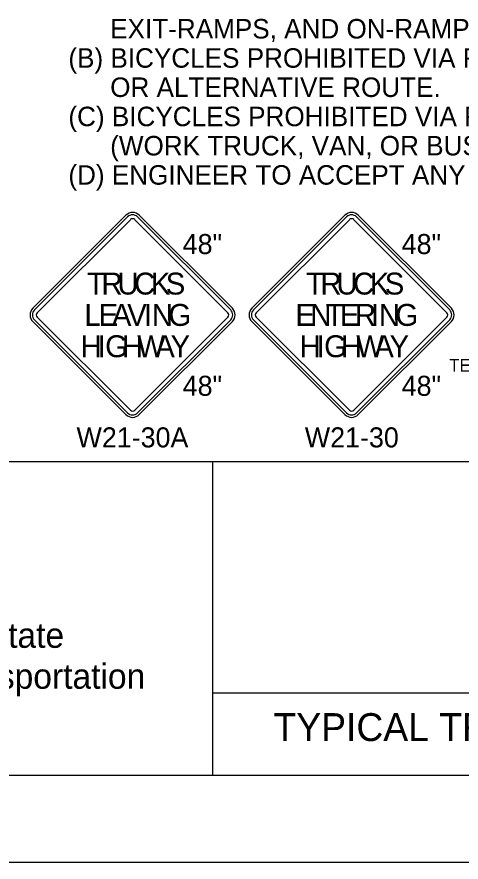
# Model space of a CAD drawing. Extents: x 99999 to 100116, y 99995 to 100013.
# Drawn here: x 100031.504 to 100033.098, y 99999.687 to 100002.723 of the extents above; entities that cross this region are included whole.
import ezdxf

# ---------------------------------------------------------------- set-up
doc = ezdxf.new("R2010")
doc.units = 0
for name, color, linetype in [('SH_GI_GeneralNotesBodyText', 7, 'Continuous'), ('SH_GI_PlotLimits', 7, 'Continuous'), ('SH_GI_SheetBorder', 7, 'Continuous'), ('SH_GI_SheetTextInCells', 7, 'Continuous'), ('SH_GI_TitleBlockText', 7, 'Continuous'), ('TR_SN_ConstructionSigns', 7, 'Continuous')]:
    doc.layers.add(name, color=color, linetype=linetype)

msp = doc.modelspace()

# ---------------------------------------------------------------- linework, layer by layer
at = {"layer": 'SH_GI_PlotLimits'}
msp.add_lwpolyline([(100019.0625, 99999.6875), (100036.0625, 99999.6875), (100036.0625, 100010.6875), (100019.0625, 100010.6875)], close=True, dxfattribs=at)
at = {"layer": 'SH_GI_SheetBorder'}
for p, q in [((100020, 100001.1259), (100035.75, 100001.1259)), ((100032.2055, 100001.1259), (100032.2055, 100000)), ((100032.2055, 100000.2955), (100035.2079, 100000.2955)), ((100020, 100000), (100035.75, 100000))]:
    msp.add_line(p, q, dxfattribs=at)
at = {"layer": 'TR_SN_ConstructionSigns'}
for p, q in [((100031.8955, 100002.0107), (100031.5613, 100001.6766)), ((100031.9014, 100002.0048), (100031.5673, 100001.6707)), ((100032.2713, 100001.6707), (100031.9372, 100002.0048)), ((100032.2773, 100001.6766), (100031.9432, 100002.0107)), ((100032.6812, 100002.0107), (100032.3471, 100001.6766)), ((100032.6871, 100002.0048), (100032.353, 100001.6707)), ((100033.057, 100001.6707), (100032.7229, 100002.0048)), ((100033.063, 100001.6766), (100032.7289, 100002.0107)), ((100031.5773, 100001.6607), (100031.9114, 100001.9948)), ((100031.9273, 100001.9948), (100032.2614, 100001.6607)), ((100032.363, 100001.6607), (100032.6971, 100001.9948)), ((100032.713, 100001.9948), (100033.0471, 100001.6607)), ((100031.9114, 100001.3107), (100031.5773, 100001.6448)), ((100032.2614, 100001.6448), (100031.9273, 100001.3107)), ((100032.6971, 100001.3107), (100032.363, 100001.6448)), ((100033.0471, 100001.6448), (100032.713, 100001.3107)), ((100031.5613, 100001.6289), (100031.8955, 100001.2948)), ((100031.5673, 100001.6349), (100031.9014, 100001.3008)), ((100031.9372, 100001.3008), (100032.2713, 100001.6349)), ((100031.9432, 100001.2948), (100032.2773, 100001.6289)), ((100032.3471, 100001.6289), (100032.6812, 100001.2948)), ((100032.353, 100001.6349), (100032.6871, 100001.3008)), ((100032.7229, 100001.3008), (100033.057, 100001.6349)), ((100032.7289, 100001.2948), (100033.063, 100001.6289))]:
    msp.add_line(p, q, dxfattribs=at)
for centre, radius, start, end in [((100031.9193, 100001.9869), 0.0338, 45, 135), ((100031.9193, 100001.9869), 0.0253, 45, 135), ((100032.705, 100001.9869), 0.0338, 45, 135), ((100032.705, 100001.9869), 0.0253, 45, 135), ((100031.9193, 100001.9869), 0.0113, 45, 135), ((100032.705, 100001.9869), 0.0113, 45, 135), ((100031.5852, 100001.6528), 0.0338, 135, 225), ((100031.5852, 100001.6528), 0.0253, 135, 225), ((100032.2534, 100001.6528), 0.0253, 315, 45), ((100032.2534, 100001.6528), 0.0338, 315, 45), ((100032.3709, 100001.6528), 0.0338, 135, 225), ((100032.3709, 100001.6528), 0.0253, 135, 225), ((100033.0391, 100001.6528), 0.0253, 315, 45), ((100033.0391, 100001.6528), 0.0338, 315, 45), ((100031.5852, 100001.6528), 0.0113, 135, 225), ((100032.2534, 100001.6528), 0.0113, 315, 45), ((100032.3709, 100001.6528), 0.0113, 135, 225), ((100033.0391, 100001.6528), 0.0113, 315, 45), ((100031.9193, 100001.3187), 0.0113, 225, 315), ((100032.705, 100001.3187), 0.0113, 225, 315), ((100031.9193, 100001.3187), 0.0338, 225, 315), ((100031.9193, 100001.3187), 0.0253, 225, 315), ((100032.705, 100001.3187), 0.0338, 225, 315), ((100032.705, 100001.3187), 0.0253, 225, 315)]:
    msp.add_arc(centre, radius, start, end, dxfattribs=at)

# ---------------------------------------------------------------- texts
at = {"layer": 'SH_GI_GeneralNotesBodyText'}
for s, p in [('EXIT-RAMPS, AND ON-RAMPS PER STATE LAW.', (100031.839, 100002.6456)), ('(B) BICYCLES PROHIBITED VIA R5-601 & R5-6 SIGNS. PROVIDE SIGNED DETOUR ', (100031.689, 100002.5406)), ('OR ALTERNATIVE ROUTE.', (100031.839, 100002.4356)), ('(C) BICYCLES PROHIBITED VIA R5-601 & R5-6 SIGNS. PROVIDE FREE SHUTTLE ', (100031.689, 100002.3306)), ('(WORK TRUCK, VAN, OR BUS OK) + CONTACT INFORMATION OR PHONE BOX.', (100031.839, 100002.2256)), ('(D) ENGINEER TO ACCEPT ANY ALTERNATIVE STRATEGIES.', (100031.689, 100002.1206))]:
    msp.add_text(s, height=0.07, rotation=360, dxfattribs=at).set_placement(p)
at = {"layer": 'SH_GI_SheetTextInCells'}
for s, p in [('Washington State', (100030.7229, 100000.4571)), ('Department of Transportation', (100030.3916, 100000.3101))]:
    msp.add_text(s, height=0.090072, dxfattribs=at).set_placement(p)
at = {"layer": 'SH_GI_TitleBlockText'}
msp.add_text('TYPICAL TRAFFIC CONTROL PLANS', height=0.1, dxfattribs=at).set_placement((100032.4251, 100000.1224))
at = {"layer": 'TR_SN_ConstructionSigns'}
for s, p in [('48"', (100032.0991, 100001.8713)), ('48"', (100032.8848, 100001.8713)), ('48"', (100032.0991, 100001.3622)), ('48"', (100032.8848, 100001.3622)), ('W21-30A', (100031.7182, 100001.1769)), ('W21-30', (100032.5373, 100001.1769))]:
    msp.add_text(s, height=0.072, rotation=360, dxfattribs=at).set_placement(p)
for s, height, p in [('T', 0.0787, (100031.7563, 100001.7259)), ('R', 0.0787, (100031.8075, 100001.7259)), ('U', 0.0787, (100031.865, 100001.7259)), ('C', 0.0787, (100031.9248, 100001.7259)), ('K', 0.0787, (100031.9847, 100001.7259)), ('S', 0.0787, (100032.0382, 100001.7259)), ('T', 0.0787, (100032.542, 100001.7259)), ('R', 0.0787, (100032.5932, 100001.7259)), ('U', 0.0787, (100032.6507, 100001.7259)), ('C', 0.0787, (100032.7106, 100001.7259)), ('K', 0.0787, (100032.7704, 100001.7259)), ('S', 0.0787, (100032.824, 100001.7259)), ('L', 0.0787, (100031.7465, 100001.6134)), ('E', 0.0787, (100031.7977, 100001.6134)), ('A', 0.0787, (100031.8449, 100001.6134)), ('V', 0.0787, (100031.9, 100001.6134)), ('I', 0.0787, (100031.9599, 100001.6134)), ('N', 0.0787, (100031.9882, 100001.6134)), ('G', 0.0787, (100032.0481, 100001.6134)), ('E', 0.0787, (100032.5034, 100001.6134)), ('N', 0.0787, (100032.557, 100001.6134)), ('T', 0.0787, (100032.6121, 100001.6134)), ('E', 0.0787, (100032.6633, 100001.6134)), ('R', 0.0787, (100032.7169, 100001.6134)), ('I', 0.0787, (100032.7743, 100001.6134)), ('N', 0.0787, (100032.8027, 100001.6134)), ('G', 0.0787, (100032.8625, 100001.6134)), ('H', 0.0787, (100031.7327, 100001.5009)), ('I', 0.0787, (100031.7941, 100001.5009)), ('G', 0.0787, (100031.8209, 100001.5009)), ('H', 0.0787, (100031.8807, 100001.5009)), ('W', 0.0787, (100031.9359, 100001.5009)), ('A', 0.0787, (100032.0004, 100001.5009)), ('Y', 0.0787, (100032.0556, 100001.5009)), ('H', 0.0787, (100032.5184, 100001.5009)), ('I', 0.0787, (100032.5798, 100001.5009)), ('G', 0.0787, (100032.6066, 100001.5009)), ('H', 0.0787, (100032.6665, 100001.5009)), ('W', 0.0787, (100032.7216, 100001.5009)), ('A', 0.0787, (100032.7862, 100001.5009)), ('Y', 0.0787, (100032.8413, 100001.5009)), ('TEXT', 0.045, (100033.0554, 100001.4491))]:
    msp.add_text(s, height=height, dxfattribs=at).set_placement(p)

doc.saveas('drawing.dxf')
